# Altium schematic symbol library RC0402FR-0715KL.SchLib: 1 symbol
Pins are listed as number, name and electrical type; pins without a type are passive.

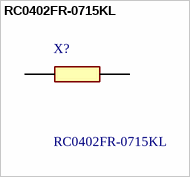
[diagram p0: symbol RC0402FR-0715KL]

## RC0402FR-0715KL
designator X?
Res SMD 0402 15K 1% 0.0625W T.C.100ppm Yageo RC Series Thick Film Surface Mount Resistor 0402 Case 15k +/-1% 0.063W +/-100ppm/C; Manufacturer_Name: Yageo Group; Geometry.Height: 0.4mm
footprint RESC1005X40N
pins: 1, 2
